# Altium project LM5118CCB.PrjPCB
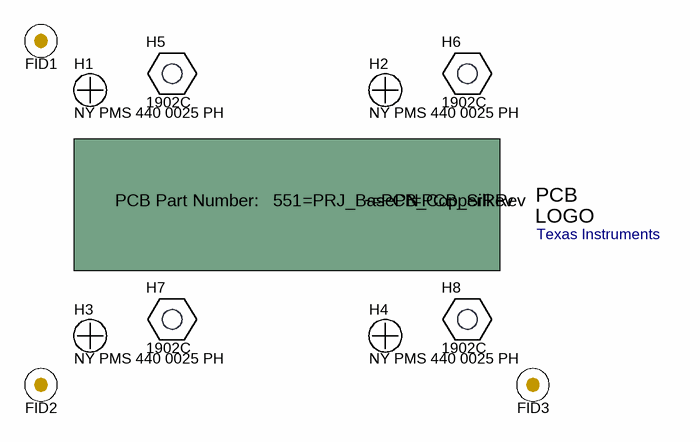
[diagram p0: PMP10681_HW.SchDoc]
TID: PMP10681; TechSupport: http://www.ti.com/support; SCH_Rev: A; PRJ_Title: LM5118 Cold Crank PCB; PRJ_Number: PMP10681; PRJ_Engineer: G Roecker; PRJ_Customer: Public Release; PCB_Rev: A; PCB_Layout: K Nielson; EVM_Orderable: LM5118CCB; CopyrightYear: 2015
2 sheets, 66 parts. Net scope: global (net labels, ports and power ports of the same name join across sheets).
Board file: PMP10681.PcbDoc
Sheets:
  PMP10681_HW.SchDoc
  PMP10681.SchDoc

## Sheet PMP10681_HW.SchDoc: LM5118 CCB EVAL BOARD
size A3; Date: Not shown in title block; ApprovedBy: Not shown in title block; CheckedBy: Not shown in title block; Author: Not shown in title block; CompanyName: Not shown in title block; DrawnBy: Not shown in title block; Engineer: Not shown in title block; Organization: Not shown in title block; Address1: Not shown in title block; Address2: Not shown in title block; Address3: Not shown in title block; Address4: Not shown in title block; DocumentNumber: 1; Revision: Use project parameter SCH_Rev; SheetNumber: 1; SheetTotal: 2; PageSetup: Record=PageOptions¦CenterHorizontal=True¦CenterVertical=True¦PrintScale=1.00¦XCorrection=1.00¦YCorrection=1.00¦PrintKind=0¦BorderSize=5000000¦LeftOffset=0¦BottomOffset=0¦Orientation=2¦PaperLength=1000¦PaperWidth=1000¦Scale=100¦PaperSource=15¦PrintQuality=600¦MediaType=1¦DitherType=10¦PaperKind=Letter¦PrintScaleMode=1

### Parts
AA?  Printed Circuit Board  (value not drawn)  (mechanical)
FID1  Fiducial  [Fiducial10-20]  (value not drawn)
FID2  Fiducial  [Fiducial10-20]  (value not drawn)
FID3  Fiducial  [Fiducial10-20]  (value not drawn)
H1  NY PMS 440 0025 PH  [NY PMS 440 0025 PH]
H2  NY PMS 440 0025 PH  [NY PMS 440 0025 PH]
H3  NY PMS 440 0025 PH  [NY PMS 440 0025 PH]
H4  NY PMS 440 0025 PH  [NY PMS 440 0025 PH]
H5  1902C  [Keystone_1902C]
H6  1902C  [Keystone_1902C]
H7  1902C  [Keystone_1902C]
H8  1902C  [Keystone_1902C]
Logo1  Texas Instruments  [TI_Stacked_Overlay_Small]  (no BOM)

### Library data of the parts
AA? = PCB: Manufacturer: TBD; PartNumber: Used in BOM Report; SymbolCreator: codlsc; U/M: EA
FID1-FID3 = Fiducial: Fiducial mark.  There is nothing to buy or mount.; SymbolCreator: codlsc
H1-H4 = NY PMS 440 0025 PH: Machine Screw, Round, #4-40 x 1/4, Nylon, Philips panhead; Manufacturer: B&F Fastener Supply; CompType: Hardware; SymbolCreator: codlsc; U/M: EA
H5-H8 = 1902C: Standoff, Hex, 0.5"L #4-40 Nylon; Manufacturer: Keystone; CompType: Hardware; U/M: EA
Logo1 = TI_Logo: Texas Instrument Corporate Signature; SymbolCreator: codlsc

## Sheet PMP10681.SchDoc: LM5118 CCB EVAL BOARD
size A3; Date: Not shown in title block; ApprovedBy: Not shown in title block; CheckedBy: Not shown in title block; Author: Not shown in title block; CompanyName: Not shown in title block; DrawnBy: Not shown in title block; Engineer: Not shown in title block; Organization: Not shown in title block; Address1: Not shown in title block; Address2: Not shown in title block; Address3: Not shown in title block; Address4: Not shown in title block; DocumentNumber: 2; Revision: Use project parameter SCH_Rev; SheetNumber: 2; SheetTotal: 2; PageSetup: Record=PageOptions¦CenterHorizontal=True¦CenterVertical=True¦PrintScale=1.09¦XCorrection=1.00¦YCorrection=1.00¦PrintKind=0¦BorderSize=5000000¦LeftOffset=0¦BottomOffset=0¦Orientation=2¦PaperLength=1000¦PaperWidth=1000¦Scale=100¦PaperSource=7¦PrintQuality=600¦MediaType=1¦DitherType=10¦PaperKind=11" x 17"¦PrintScaleMode=1
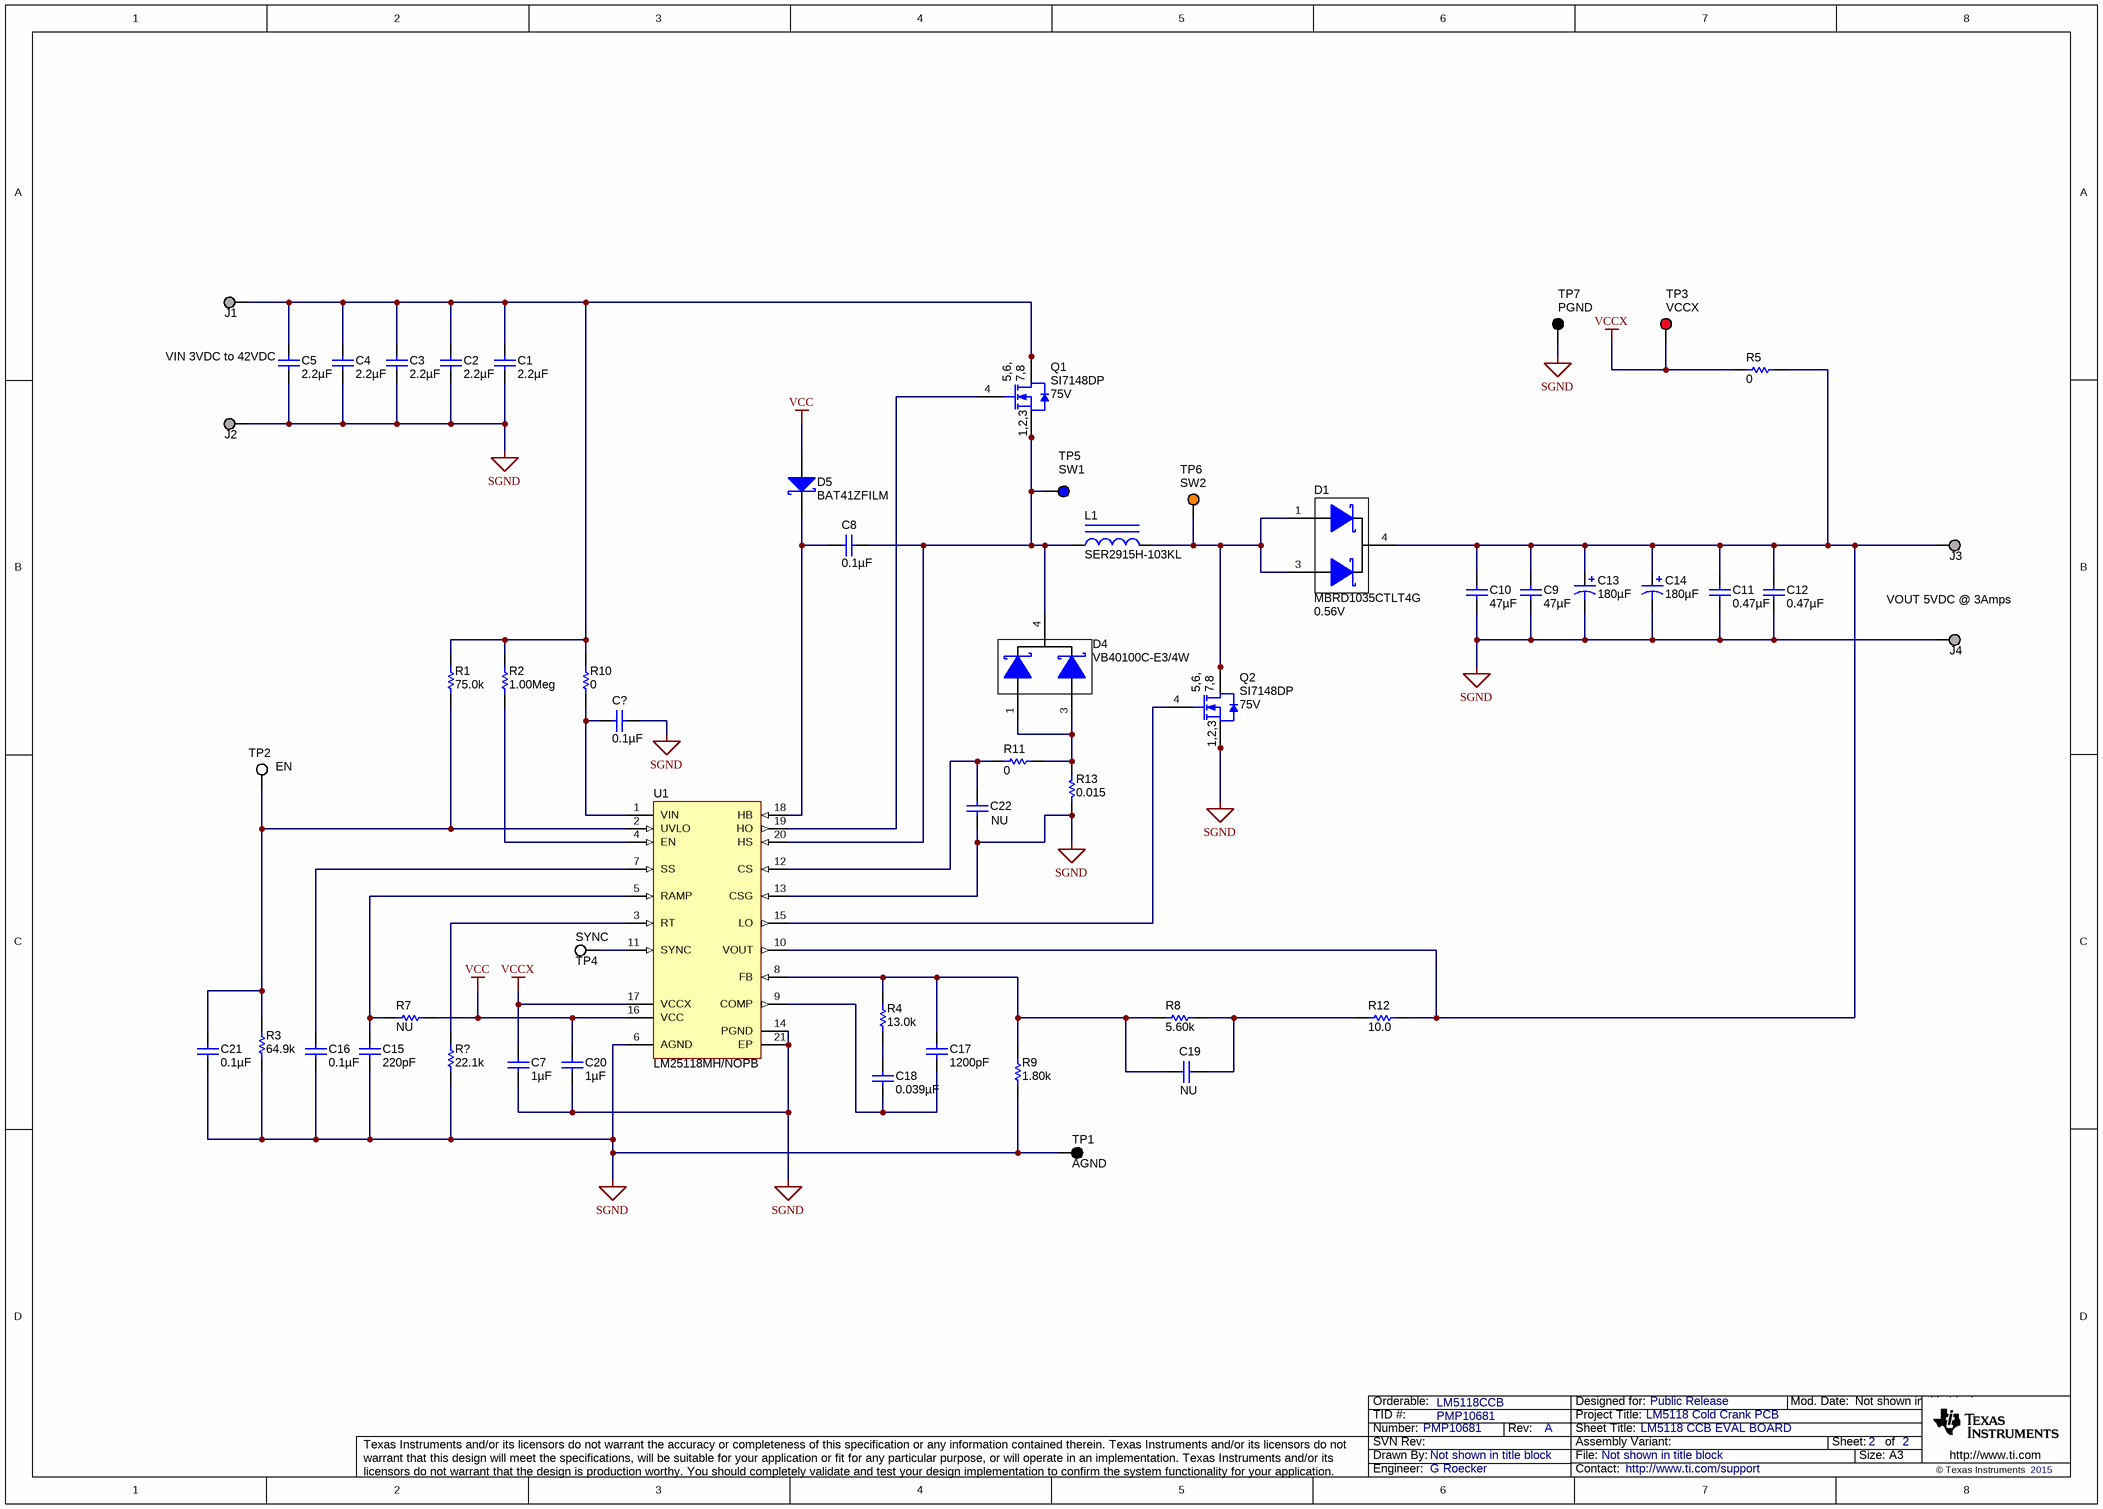
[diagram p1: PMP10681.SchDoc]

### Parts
C1  ValueDisplayed: 2.2µF  [1812]  (hidden comment: C4532X7R2A225M)
C2  ValueDisplayed: 2.2µF  [1812]  (hidden comment: C4532X7R2A225M)
C3  ValueDisplayed: 2.2µF  [1812]  (hidden comment: C4532X7R2A225M)
C4  ValueDisplayed: 2.2µF  [1812]  (hidden comment: C4532X7R2A225M)
C5  ValueDisplayed: 2.2µF  [1812]  (hidden comment: C4532X7R2A225M)
C7  ValueDisplayed: 1µF  [0805_HV]  (hidden comment: GRM219R71E105KA88D)
C8  ValueDisplayed: 0.1µF  [0603_HV]  (hidden comment: GRM188R72A104KA35D)
C9  ValueDisplayed: 47µF  [1210]  (hidden comment: GRM32ER61C476KE15L)
C10  ValueDisplayed: 47µF  [1210]  (hidden comment: GRM32ER61C476KE15L)
C11  ValueDisplayed: 0.47µF  [1206]  (hidden comment: 12063C474KAT2A)
C12  ValueDisplayed: 0.47µF  [1206]  (hidden comment: 12063C474KAT2A)
C13  ValueDisplayed: 180µF  [CAPSMT_62_J80]  (hidden comment: APXH160ARA181MJ80G)
C14  ValueDisplayed: 180µF  [CAPSMT_62_J80]  (hidden comment: APXH160ARA181MJ80G)
C15  ValueDisplayed: 220pF  [0603]  (hidden comment: GRM1885C2A331JA01D)
C16  ValueDisplayed: 0.1µF  [0603]  (hidden comment: GRM188R72A104KA35D)
C17  ValueDisplayed: 1200pF  [0603]  (hidden comment: GRM188R72A222KA01D)
C18  ValueDisplayed: 0.039µF  [0603]  (hidden comment: C1608X7R2A472K)
C19  value NU  [0603]  (hidden comment: Used in BOM report)
C20  ValueDisplayed: 1µF  [0805_HV]  (hidden comment: GRM219R71E105KA88D)
C21  ValueDisplayed: 0.1µF  [0603]  (hidden comment: GRM188R72A104KA35D)
C22  value NU  [0603]  (hidden comment: Used in BOM report)
C?  ValueDisplayed: 0.1µF  [0805_HV]  (hidden comment: C0805C104K1RACTU)
D1  MBRD1035CTLT4G  value 0.56V  [DPAK]
D4  VB40100C-E3/4W  [DDPAK]
D5  BAT41ZFILM  [SOD-123]
J1  Suggest using a net name here  [Keystone1503-2]  (value not drawn)
J2  Suggest using a net name here  [Keystone1503-2]  (value not drawn)
J3  Suggest using a net name here  [Keystone1503-2]  (value not drawn)
J4  Suggest using a net name here  [Keystone1503-2]  (value not drawn)
L1  SER2915H-103KL  [SER2915]
Q1  SI7148DP  value 75V  [PowerPAK_SO-8]
Q2  SI7148DP  value 75V  [PowerPAK_SO-8]
R1  value 75.0k  [0805_HV]  (hidden comment: CRCW080575K0FKEA)
R2  value 1.00Meg  [0805_HV]  (hidden comment: CRCW08051M00FKEA)
R3  ValueDisplayed: 64.9k  [0603]  (hidden comment: RT0603BRD0729K4L)
R4  ValueDisplayed: 13.0k  [0603]  (hidden comment: CRCW060310K0FKEA)
R5  value 0  [0805_HV]  (hidden comment: CRCW08050000Z0EA)
R7  value NU  [0603]  (hidden comment: Used in BOM report)
R8  ValueDisplayed: 5.60k  [0603]  (hidden comment: CRCW06032K67FKEA)
R9  ValueDisplayed: 1.80k  [0603]  (hidden comment: CRCW0603309RFKEA)
R10  value 0  [1206]  (hidden comment: CRCW12060000Z0EA)
R11  value 0  [0603]  (hidden comment: CRCW06030000Z0EA)
R12  value 10.0  [0603]  (hidden comment: CRCW060310R0FKEA)
R13  value 0.015  [3008M - Silk]  (hidden comment: RL7520WT-R015-G)
R?  ValueDisplayed: 22.1k  [0603]  (hidden comment: CRCW060316K2FKEA)
TP1  AGND  [Keystone5011]
TP2  EN  [Keystone5012]
TP3  VCCX  [Keystone5010]
TP4  SYNC  [Keystone5012]
TP5  SW1  [Keystone5127]
TP6  SW2  [Keystone5013]
TP7  PGND  [Keystone5011]
U1  LM25118MH/NOPB  [MXA20A_N_NoVias]

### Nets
SGND: C1.2 C2.2 C3.2 C4.2 C5.2 C7.2 C9.2 C10.2 C11.2 C12.2 C13.2(-) C14.2(-) C15.2 C16.2 C20.2 C21.2 C22.2 C?.1 J2.1 J4.1 Q2.1(S) Q2.2(S) Q2.3(S) R3.1 R9.1 R13.2 R?.1 TP1.1 TP7.1 U1.6(AGND) U1.13(CSG) U1.14(PGND) U1.21(EP)
VCC: C20.1 D5.2(A) R7.2 U1.16(VCC)
VCCX: C7.1 R5.1 TP3.1 U1.17(VCCX)
NetC1_1: C1.1 C2.1 C3.1 C4.1 C5.1 J1.1 Q1.5(D) Q1.6(D) Q1.7(D) Q1.8(D) Q1.9(D) R1.2 R2.2 R10.2
NetC8_1: C8.1 D5.1(K) U1.18(HB)
NetC8_2: C8.2 D4.4(K) L1.2 Q1.1(S) Q1.2(S) Q1.3(S) TP5.1 U1.20(HS)
NetC9_1: C9.1 C10.1 C11.1 C12.1 C13.1(+) C14.1(+) D1.4(K) J3.1 R5.2 R12.2 U1.10(VOUT)
NetC15_1: C15.1 R7.1 U1.5(RAMP)
NetC16_1: C16.1 U1.7(SS)
NetC17_1: C17.1 C19.2 R4.2 R8.1 R9.2 U1.8(FB)
NetC17_2: C17.2 C18.2 U1.9(COMP)
NetC18_1: C18.1 R4.1
NetC19_1: C19.1 R8.2 R12.1
NetC21_1: C21.1 R1.1 R3.2 TP2.1 U1.2(UVLO)
NetC22_1: C22.1 R11.1 U1.12(CS)
NetC?_2: C?.2 R10.1 U1.1(VIN)
NetD1_1: D1.1(A) D1.3(A) L1.1 Q2.5(D) Q2.6(D) Q2.7(D) Q2.8(D) Q2.9(D) TP6.1
NetD4_1: D4.1(A) D4.3(A) R11.2 R13.1
NetQ1_4: Q1.4(G) U1.19(HO)
NetQ2_4: Q2.4(G) U1.15(LO)
NetR2_1: R2.1 U1.4(EN)
NetR?_2: R?.2 U1.3(RT)
NetTP4_1: TP4.1 U1.11(SYNC)

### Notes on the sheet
- (near C5) VIN 3VDC to 42VDC
- VOUT 5VDC @ 3Amps

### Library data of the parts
C1-C5 = C4532X7R2A225M: CAP, CERM, 2.2uF, 100V, +/-20%, X7R, 1812; Manufacturer: TDK; Polarized: N; CompType: Capacitor; U/M: EA; Cap_F: 0.0000022; Tolerance_%: 20; ESR_Ohm: 0.001; Value1: 0.001 ohm; VDC_V: 100; TaMin_C: -55; TaMax_C: 125
C7 C20 = GRM219R71E105KA88D: CAP, CERM, 1uF, 25V, +/-10%, X7R, 0805; Manufacturer: MuRata; Polarized: N; CompType: Capacitor; U/M: EA; Cap_F: 0.000001; Tolerance_%: 10; VDC_V: 25; TaMin_C: -55; TaMax_C: 125; Cap_Case: 0805
C8 = GRM188R72A104KA35D: CAP, CERM, 0.1uF, 100V, +/-10%, X7R, 0603; Manufacturer: MuRata; Polarized: N; CompType: Capacitor; U/M: EA; Cap_F: 0.0000001; Tolerance_%: 10; VDC_V: 100; TaMin_C: -55; TaMax_C: 125; Cap_Case: 0603
C9 C10 = GRM32ER61C476KE15L: CAP, CERM, 47uF, 16V, +/-10%, X5R, 1210; Manufacturer: MuRata; Polarized: N; CompType: Capacitor; U/M: EA; Cap_F: 0.000047; Tolerance_%: 10; VDC_V: 16; TaMin_C: -55; TaMax_C: 85
C11 C12 = 12063C474KAT2A: CAP, CERM, 0.47uF, 25V, +/-10%, X7R, 1206; Manufacturer: AVX; Polarized: N; CompType: Capacitor; U/M: EA; Cap_F: 0.00000047; Tolerance_%: 10; ESR_Ohm: 0.018; Value1: 0.018 ohm; VDC_V: 25; TaMin_C: -55; TaMax_C: 125
C13 C14 = APXH160ARA181MJ80G: CAP, AL, 180uF, 16V, +/-20%, 0.026 ohm, SMD; Manufacturer: Nippon Chemi-Con; Polarized: Y; CompType: Capacitor; U/M: EA; Cap_F: 0.00018; Tolerance_%: 20; VDC_V: 16; ESR_Ohm: 0.026; IRMS_A: 3.02; TaMin_C: -55; TaMax_C: 125; Cap_Case: J80
C15 = GRM188R71H221KA01D: CAP, CERM, 220 pF, 50 V, +/- 10%, X7R, 0603; Manufacturer: MuRata; Polarized: N; CompType: Capacitor; Value: 220pF; U/M: EA; Cap_F: 0.00000000022; Tolerance_%: 10; Value1: Unknown; VDC_V: 50; Value2: 50V; TaMin_C: -55; TaMax_C: 125
C16 C21 = GRM188R72A104KA35D: CAP, CERM, 0.1uF, 100V, +/-10%, X7R, 0603; Manufacturer: MuRata; Polarized: N; CompType: Capacitor; U/M: EA; Cap_F: 0.0000001; Tolerance_%: 10; VDC_V: 100; TaMin_C: -55; TaMax_C: 125
C17 = GRM188R71H122KA01D: CAP, CERM, 1200 pF, 50 V, +/- 10%, X7R, 0603; Manufacturer: MuRata; Polarized: N; CompType: Capacitor; Value: 1200pF; U/M: EA; Cap_F: 0.0000000012; Tolerance_%: 10; Value1: Unknown; VDC_V: 50; Value2: 50V; TaMin_C: -55; TaMax_C: 125
C18 = GRM188R71E393KA01D: CAP, CERM, 0.039 µF, 25 V, +/- 10%, X7R, 0603; Manufacturer: MuRata; Polarized: N; CompType: Capacitor; Value: 0.039uF; U/M: EA; Cap_F: 0.000000039; Tolerance_%: 10; Value1: Unknown; VDC_V: 25; Value2: 25V; TaMin_C: -55; TaMax_C: 125
C19 C22 = Capacitor: CAP, CERM, xxxF, xxV, [Dielectric], xx%, [Package]; Polarized: N; U/M: EA
C? = C0805C104K1RACTU: CAP, CERM, 0.1uF, 100V, +/-10%, X7R, 0805; Manufacturer: Kemet; Polarized: N; CompType: Capacitor; U/M: EA; Cap_F: 0.0000001; Tolerance_%: 10; ESR_Ohm: 0.064; Value1: 0.064 ohm; VDC_V: 100; IRMS_A: 1.64; TaMin_C: -55; TaMax_C: 125; Cap_Case: 0805
D1 = MBRD1035CTLT4G: Diode, Schottky, 35V, 10A, DPAK; Manufacturer: ON Semiconductor; U/M: EA; Vf_V: 0.56; Io_A: 10; Vr_V: 35; TJmax_C: 150; RJC_CperW: 3
D4 = MBRB20100CTT4G: Diode, Schottky, 100V, 20A, DDPAK; Manufacturer: Vishay; Value: 0.73V; U/M: EA; Vf_V: 0.73; Io_A: 20; Vr_V: 100; TJmax_C: 150; RJC_CperW: 2
D5 = BAT41ZFILM: Diode, Schottky, 100V, 0.2A, SOD-123; Manufacturer: ST Microelectronics; Value: 1V; U/M: EA; Vf_V: 1; Io_A: 0.2; Vr_V: 100; TJmax_C: 150
J1-J4 = 1503-2: Terminal, Turret, TH, Double; Manufacturer: Keystone; CompType: Turret Terminal; U/M: EA
L1 = 7443630700: Inductor, Shielded Drum Core, Mn-Zn, 7 µH, 21 A, 0.005608 ohm, SMD; Manufacturer: Wurth Elektronik; Value: 7uH; ValueDisplayed: 7µH; Ind_H: 7.0E-6; Imax_A: 21; Irms: 21A @ 50C rise; Isat: 30A @ 30% inductance drop; Value2: 21A
Q1 Q2 = SI7148DP: MOSFET, N-CH, 75V, 12A, PowerPAK SO-8; Manufacturer: Vishay-Siliconix; U/M: EA; ChType: N; VdsMax_V: 75; Value1: 0.012 ohm; Rdson45_Ohm: 0.012; Value2: 68 nC; QgTyp_nC: 68; Vgs_V: 20; IdsMax_A: 12
R1 = CRCW080575K0FKEA: RES, 75.0k ohm, 1%, 0.125W, 0805; Manufacturer: Vishay-Dale; CompType: Resistor; Res_ohm: 75000; Value_Code: 75k0; Tolerance_%: 1; Power_W: 0.125; VDC_V: 150; TempCo: 100 ppm/C; EIA_Code: E96; U/M: EA
R2 = CRCW08051M00FKEA: RES, 1.00Meg ohm, 1%, 0.125W, 0805; Manufacturer: Vishay-Dale; CompType: Resistor; Res_ohm: 1000000; Value_Code: 1M00; Tolerance_%: 1; Power_W: 0.125; VDC_V: 150; TempCo: 100 ppm/C; EIA_Code: E96; U/M: EA
R3 = RC0603FR-0764K9L: RES, 64.9 k, 1%, 0.1 W, 0603; Manufacturer: Yageo America; CompType: Resistor; Value: 64.9k; Res_ohm: 64900; Value_Code: 64k9; Tolerance_%: 1; Power_W: 0.1; Value2: 0.1W; VDC_V: 150; TempCo: 200 ppm/C; EIA_Code: E96; U/M: EA
R4 = CRCW060313K0FKEA: RES, 13.0 k, 1%, 0.1 W, 0603; Manufacturer: Vishay-Dale; CompType: Resistor; Value: 13.0k; Res_ohm: 13000; Value_Code: 13k0; Tolerance_%: 1; Power_W: 0.1; Value2: 0.1W; VDC_V: 75; TempCo: 100 ppm/C; EIA_Code: E96; U/M: EA
R5 = CRCW08050000Z0EA: RES, 0 ohm, 5%, 0.125W, 0805; Manufacturer: Vishay-Dale; CompType: Resistor; U/M: EA; Value_Code: 0000; Tolerance_%: 5; Power_W: 0.125; VDC_V: 150; TempCo: 200 ppm/C; EIA_Code: E24
R7 = Resistor: RES, xxx ohm, x%, xW, [PackageReference]; U/M: EA
R8 = RC0603FR-075K6L: RES, 5.60 k, 1%, 0.1 W, 0603; Manufacturer: Yageo America; CompType: Resistor; Value: 5.60k; Res_ohm: 5600; Value_Code: 5k60; Tolerance_%: 1; Power_W: 0.1; Value2: 0.1W; VDC_V: 150; TempCo: 200 ppm/C; U/M: EA
R9 = RC0603FR-071K8L: RES, 1.80 k, 1%, 0.1 W, 0603; Manufacturer: Yageo America; CompType: Resistor; Value: 1.80k; Res_ohm: 1800; Value_Code: 1k80; Tolerance_%: 1; Power_W: 0.1; Value2: 0.1W; VDC_V: 150; TempCo: 200 ppm/C; U/M: EA
R10 = CRCW12060000Z0EA: RES, 0 ohm, 5%, 0.25W, 1206; Manufacturer: Vishay-Dale; CompType: Resistor; Value_Code: 0000; Tolerance_%: 5; Power_W: 0.25; VDC_V: 200; TempCo: 200 ppm/C; EIA_Code: E24; U/M: EA
R11 = CRCW06030000Z0EA: RES, 0 ohm, 5%, 0.1W, 0603; Manufacturer: Vishay-Dale; CompType: Resistor; Value_Code: 0000; Tolerance_%: 5; Power_W: 0.1; VDC_V: 75; TempCo: 200 ppm/C; EIA_Code: E24; U/M: EA
R12 = CRCW060310R0FKEA: RES, 10.0 ohm, 1%, 0.1W, 0603; Manufacturer: Vishay-Dale; CompType: Resistor; Res_ohm: 10; Value_Code: 10R0; Tolerance_%: 1; Power_W: 0.1; VDC_V: 75; TempCo: 100 ppm/C; EIA_Code: E96; U/M: EA
R13 = RL7520WT-R020-F: RES, 0.015 ohm, 1%, 2W, 3008; Manufacturer: Susumu Co Ltd; CompType: Resistor; Value_Code: R015; Tolerance_%: 1; Power_W: 2; TempCo: 350 ppm/C; EIA_Code: E96; U/M: EA
R? = CRCW060322K1FKEA: RES, 22.1 k, 1%, 0.1 W, 0603; Manufacturer: Vishay-Dale; CompType: Resistor; Value: 22.1k; Res_ohm: 22100; Value_Code: 22k1; Tolerance_%: 1; Power_W: 0.1; Value2: 0.1W; VDC_V: 75; TempCo: 100 ppm/C; EIA_Code: E96; U/M: EA
TP1 TP7 = 5011: Test Point, TH, Multipurpose, Black; Manufacturer: Keystone; CompType: Test Point Loop; U/M: EA
TP2 TP4 = 5012: Test Point, TH, Multipurpose, White; Manufacturer: Keystone; CompType: Test Point Loop; U/M: EA
TP3 = 5010: Test Point, TH, Multipurpose, Red; Manufacturer: Keystone; CompType: Test Point Loop; U/M: EA
TP5 = 5127: Test Point, TH, Multipurpose, Blue; Manufacturer: Keystone; CompType: Test Point Loop; U/M: EA
TP6 = 5013: Test Point, TH, Multipurpose, Orange; Manufacturer: Keystone; CompType: Test Point Loop; U/M: EA
U1 = LM5118MH/NOPB: Wide Voltage Range Buck-Boost Controller, 20-pin TSSOP-EP, Pb-Free; Manufacturer: National Semiconductor; PackageTopMarking: NSUZXYTT*LM5118*MH; PowerWise: Y; CompType: Switcher

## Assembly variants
001: not fitted FID1 FID2 FID3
